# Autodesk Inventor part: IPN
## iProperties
Author: Jan-Steinar
Shininess: 20.0
PropertySet Name: _Private Model Information
Created: 2001-01
Part Number: IPN
Document SubType Name: Modeling
Designer: Jan-Steinar
Control State: 0
Master: False
Checked Out: False
PropertySet Name: Design Tracking Control
Density: 0.0
Volumn: 0.0
Area: 0.0
PropertySet Name: Model Information
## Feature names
1. Extrusion1
